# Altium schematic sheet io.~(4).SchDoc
size Letter
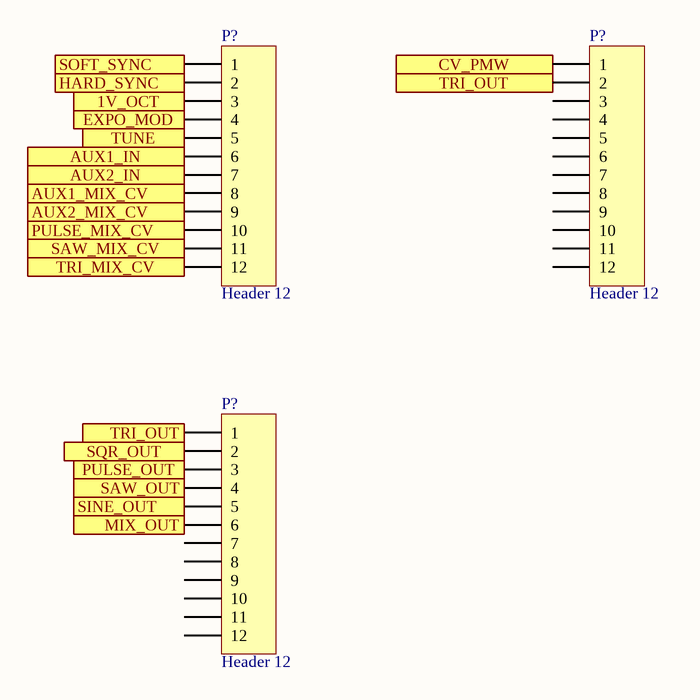
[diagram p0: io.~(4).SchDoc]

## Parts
(Parts that share a designator on the sheet are numbered #1, #2 ... from top to bottom, then left to right.)
P?#1  Header 12  [HDR1X12]
P?#2  Header 12  [HDR1X12]
P?#3  Header 12  [HDR1X12]

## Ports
1V_OCT, AUX1_IN, AUX1_MIX_CV, AUX2_IN, AUX2_MIX_CV, CV_PMW, EXPO_MOD, HARD_SYNC, MIX_OUT, PULSE_MIX_CV, PULSE_OUT, SAW_MIX_CV, SAW_OUT, SINE_OUT, SOFT_SYNC, SQR_OUT, TRI_MIX_CV, TRI_OUT, TUNE

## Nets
1V_OCT: P?#1.3 ; port 1V_OCT
AUX1_IN: P?#1.6 ; port AUX1_IN
AUX1_MIX_CV: P?#1.8 ; port AUX1_MIX_CV
AUX2_IN: P?#1.7 ; port AUX2_IN
AUX2_MIX_CV: P?#1.9 ; port AUX2_MIX_CV
CV_PMW: P?#2.1 ; port CV_PMW
EXPO_MOD: P?#1.4 ; port EXPO_MOD
HARD_SYNC: P?#1.2 ; port HARD_SYNC
MIX_OUT: P?#3.6 ; port MIX_OUT
PULSE_MIX_CV: P?#1.10 ; port PULSE_MIX_CV
PULSE_OUT: P?#3.3 ; port PULSE_OUT
SAW_MIX_CV: P?#1.11 ; port SAW_MIX_CV
SAW_OUT: P?#3.4 ; port SAW_OUT
SINE_OUT: P?#3.5 ; port SINE_OUT
SOFT_SYNC: P?#1.1 ; port SOFT_SYNC
SQR_OUT: P?#3.2 ; port SQR_OUT
TRI_MIX_CV: P?#1.12 ; port TRI_MIX_CV
TRI_OUT: P?#2.2 P?#3.1 ; port TRI_OUT
TUNE: P?#1.5 ; port TUNE

Not connected (* = marked no-connect by the designer): P?#2 3 4 5 6 7 8 9 10 11 12; P?#3 7 8 9 10 11 12

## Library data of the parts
P?#1-P?#3 = Header 12: Header, 12-Pin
